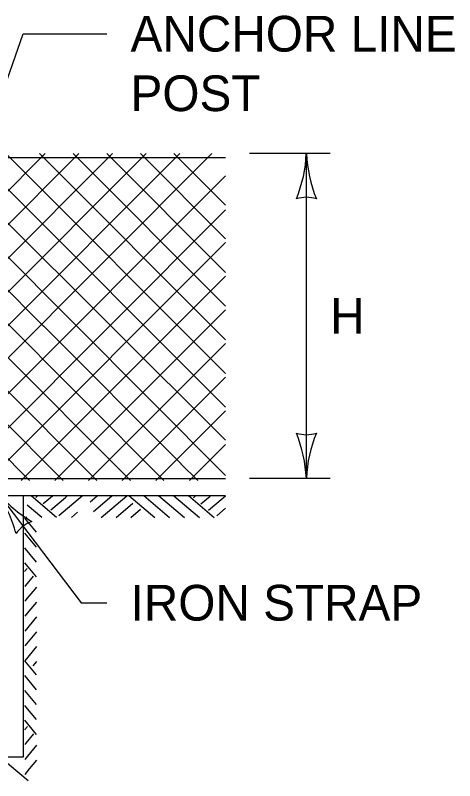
# Model space of a CAD drawing. Extents: x 49973.1 to 50021, y 49987.6 to 50015.4.
# Drawn here: x 50007.121 to 50007.86, y 49991.933 to 49993.219 of the extents above; entities that cross this region are included whole.
import ezdxf

# ---------------------------------------------------------------- set-up
doc = ezdxf.new("R2010")
doc.units = 0
for name, color, linetype in [('Level 1', 7, 'Continuous'), ('Level 2', 7, 'Continuous'), ('Level 3', 7, 'Continuous')]:
    doc.layers.add(name, color=color, linetype=linetype)

msp = doc.modelspace()

# ---------------------------------------------------------------- linework, layer by layer
at = {"layer": 'Level 1'}
for p, q in [((50007.1451, 49992.4372), (50006.5959, 49992.9864)), ((50007.1711, 49992.9864), (50006.6219, 49992.4372)), ((50007.2017, 49992.4372), (50006.6525, 49992.9864)), ((50007.2276, 49992.9864), (50006.6784, 49992.4372)), ((50007.258, 49992.4372), (50006.7091, 49992.9864)), ((50007.2842, 49992.9864), (50006.735, 49992.4372)), ((50007.3147, 49992.4372), (50006.7655, 49992.9864)), ((50007.3409, 49992.9864), (50006.7917, 49992.4372)), ((50007.3709, 49992.4372), (50006.8221, 49992.9864)), ((50007.3974, 49992.9864), (50006.9062, 49992.4953)), ((50007.4744, 49992.4458), (50006.9353, 49992.9864)), ((50007.4516, 49992.9864), (50006.9504, 49992.4852)), ((50007.4744, 49992.5051), (50006.9905, 49992.9864)), ((50007.4744, 49992.5603), (50007.0483, 49992.9864)), ((50007.4744, 49992.6169), (50007.1049, 49992.9864)), ((50007.4744, 49992.6735), (50007.1615, 49992.9864)), ((50007.4744, 49992.73), (50007.2181, 49992.9864)), ((50007.4744, 49992.7866), (50007.2747, 49992.9864)), ((50007.4744, 49992.8432), (50007.3313, 49992.9864)), ((50007.4744, 49992.8996), (50007.3877, 49992.9864)), ((50007.0491, 49992.9796), (50007.4744, 49992.9796)), ((50007.4744, 49992.9491), (50006.9957, 49992.4702)), ((50007.169, 49992.6959), (50006.9729, 49992.892)), ((50007.4744, 49992.8918), (50007.0198, 49992.4372)), ((50007.4744, 49992.8373), (50007.0743, 49992.4372)), ((50007.4744, 49992.7807), (50007.1309, 49992.4372)), ((50007.4744, 49992.7241), (50007.1875, 49992.4372)), ((50007.3997, 49992.4652), (50007.1681, 49992.6969)), ((50007.4744, 49992.6675), (50007.2441, 49992.4372)), ((50007.4744, 49992.6109), (50007.3007, 49992.4372)), ((50007.2383, 49992.5446), (50007.237, 49992.5433)), ((50007.4744, 49992.5545), (50007.3571, 49992.4372)), ((50007.4744, 49992.4979), (50007.4137, 49992.4372)), ((50007.4279, 49992.4372), (50007.3994, 49992.4656)), ((50005.6017, 49992.4409), (50007.4744, 49992.4409)), ((50007.4744, 49992.4116), (50005.7447, 49992.4116)), ((50007.1344, 49992.4116), (50007.1344, 49991.9725)), ((50007.1903, 49992.3753), (50007.1474, 49992.4114)), ((50007.1553, 49992.4088), (50007.1584, 49992.4114)), ((50007.168, 49992.3986), (50007.1834, 49992.4114)), ((50007.1805, 49992.3881), (50007.2051, 49992.4087)), ((50007.1944, 49992.3787), (50007.2267, 49992.4058)), ((50007.2051, 49992.4087), (50007.2084, 49992.4114)), ((50007.2267, 49992.4058), (50007.2335, 49992.4114)), ((50007.2468, 49992.4016), (50007.2585, 49992.4114)), ((50007.2524, 49992.3854), (50007.2835, 49992.4114)), ((50007.2653, 49992.3753), (50007.3084, 49992.4114)), ((50007.2653, 49992.3753), (50007.3084, 49992.4114)), ((50007.3554, 49992.3748), (50007.3119, 49992.4114)), ((50007.3804, 49992.3748), (50007.3369, 49992.4114)), ((50007.4054, 49992.3748), (50007.3619, 49992.4114)), ((50007.4304, 49992.3748), (50007.3874, 49992.4109)), ((50007.4554, 49992.3748), (50007.4119, 49992.4114)), ((50007.4204, 49992.4083), (50007.4241, 49992.4114)), ((50007.4331, 49992.3981), (50007.4488, 49992.4112)), ((50007.4456, 49992.3876), (50007.4702, 49992.4082)), ((50007.4702, 49992.4082), (50007.4741, 49992.4114)), ((50007.1653, 49992.3753), (50007.1407, 49992.3959)), ((50007.2903, 49992.3753), (50007.3187, 49992.3991)), ((50007.3153, 49992.3753), (50007.3316, 49992.389)), ((50007.4595, 49992.3782), (50007.4744, 49992.3907)), ((50007.1403, 49992.3753), (50007.139, 49992.3764)), ((50007.2153, 49992.3753), (50007.2257, 49992.384)), ((50007.1567, 49992.3505), (50007.1368, 49992.3742)), ((50007.1567, 49992.3255), (50007.1368, 49992.3492)), ((50007.1383, 49992.3225), (50007.1368, 49992.3242)), ((50007.1567, 49992.3005), (50007.1383, 49992.3225)), ((50007.1567, 49992.2755), (50007.1368, 49992.2992)), ((50007.1409, 49992.2895), (50007.1367, 49992.2845)), ((50007.1511, 49992.2768), (50007.138, 49992.2611)), ((50007.138, 49992.2611), (50007.1368, 49992.2596)), ((50007.1567, 49992.2584), (50007.141, 49992.2397)), ((50007.141, 49992.2397), (50007.1368, 49992.2346)), ((50007.1567, 49992.2333), (50007.1439, 49992.2181)), ((50007.1439, 49992.2181), (50007.1368, 49992.2095)), ((50007.1567, 49992.2083), (50007.1368, 49992.1845)), ((50007.1567, 49992.1833), (50007.1368, 49992.1595)), ((50007.1567, 49992.1584), (50007.1368, 49992.1347)), ((50007.1567, 49992.111), (50007.1368, 49992.1347)), ((50007.1567, 49992.1333), (50007.1506, 49992.1261)), ((50007.1567, 49992.086), (50007.1368, 49992.1097)), ((50007.1567, 49992.061), (50007.1368, 49992.0847)), ((50007.1388, 49992.0574), (50007.1368, 49992.0597)), ((50007.1567, 49992.036), (50007.1388, 49992.0574)), ((50007.1567, 49992.011), (50007.1368, 49992.0347)), ((50007.1372, 49992.0194), (50007.1368, 49992.0189)), ((50007.1414, 49992.0244), (50007.1372, 49992.0194)), ((50007.1516, 49992.0117), (50007.1385, 49991.996)), ((50007.1385, 49991.996), (50007.1368, 49991.9939)), ((50007.1567, 49991.9927), (50007.1415, 49991.9746)), ((50007.1344, 49991.9725), (50007.0044, 49991.9725)), ((50007.1424, 49991.9332), (50007.0971, 49991.9713)), ((50007.1415, 49991.9746), (50007.1368, 49991.9689)), ((50007.1567, 49991.9676), (50007.1444, 49991.953)), ((50007.1444, 49991.953), (50007.1368, 49991.9438))]:
    msp.add_line(p, q, dxfattribs=at)
at = {"layer": 'Level 3'}
for p, q in [((50007.069, 49993.0014), (50007.1341, 49993.1877)), ((50007.1341, 49993.1877), (50007.2747, 49993.1877)), ((50007.6503, 49992.9864), (50007.5144, 49992.9864)), ((50007.6103, 49992.4409), (50007.6103, 49992.9864)), ((50007.6503, 49992.4409), (50007.5144, 49992.4409)), ((50007.0896, 49992.4188), (50007.2316, 49992.2321)), ((50007.2316, 49992.2321), (50007.2747, 49992.2321))]:
    msp.add_line(p, q, dxfattribs=at)
for centre, radius, start, end in [((50007.3881, 49992.9956), 0.2223, 337.456, 357.6395), ((50007.843, 49992.9979), 0.233, 182.8273, 202.0772), ((50007.6103, 49992.8582), 0.0548, 72.1388, 107.8612), ((50007.6103, 49992.5691), 0.0548, 252.1388, 287.8612), ((50007.3775, 49992.4294), 0.233, 2.8273, 22.0772), ((50007.8324, 49992.4318), 0.2223, 157.456, 177.6395), ((50006.9072, 49992.2916), 0.2223, 14.7287, 34.9122), ((50007.2678, 49992.5689), 0.233, 220.1, 239.3498), ((50007.1672, 49992.3168), 0.0548, 109.4115, 145.1338)]:
    msp.add_arc(centre, radius, start, end, dxfattribs=at)

# ---------------------------------------------------------------- texts
at = {"layer": 'Level 2'}
for s, p in [('ANCHOR LINE', (50007.3147, 49993.1577)), ('POST', (50007.3147, 49993.0577)), ('H', (50007.6503, 49992.6837)), ('IRON STRAP', (50007.3147, 49992.2021))]:
    msp.add_text(s, height=0.06, dxfattribs=at).set_placement(p)

doc.saveas('drawing.dxf')
